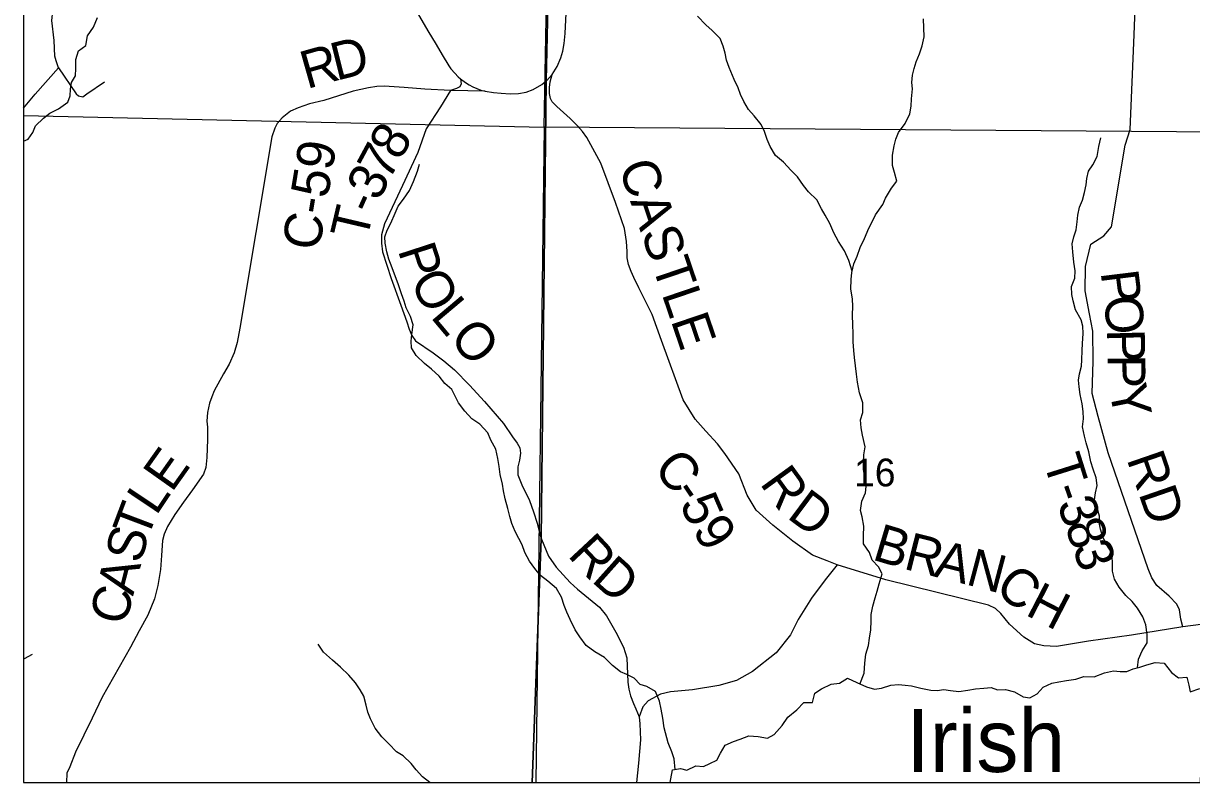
# Model space of a CAD drawing. Extents: x -3.6 to 34, y 0 to 32.8.
# Drawn here: x -3.63 to -1.871, y 26.043 to 27.186 of the extents above; entities that cross this region are included whole.
import ezdxf

# ---------------------------------------------------------------- set-up
doc = ezdxf.new("R2010")
doc.units = 0
for name, color, linetype in [('GM_X_Corporation', 7, 'Continuous'), ('GM_X_County_Road', 7, 'Continuous'), ('GM_X_County_Road_Text', 7, 'Continuous'), ('GM_X_Minor_River', 7, 'Continuous'), ('GM_X_Minor_River_Text', 7, 'Continuous'), ('GM_X_Section_Text', 7, 'Continuous'), ('GM_X_State_Route', 7, 'Continuous'), ('GM_X_Township_Road', 7, 'Continuous'), ('GM_X_Township_Road_Text', 7, 'Continuous'), ('SH_Data', 7, 'Continuous')]:
    doc.layers.add(name, color=color, linetype=linetype)

msp = doc.modelspace()

# ---------------------------------------------------------------- linework, layer by layer
at = {"layer": 'GM_X_Corporation'}
for points in [[(3.1705, 28.9337), (3.1705, 32.8429), (-3.6295, 32.8429), (-3.6295, 26.0429), (2.3706, 26.0429), (2.3712, 26.0804), (2.3716, 26.1248), (2.3732, 26.2253), (2.3789, 26.6097), (2.3911, 27.5117), (2.3952, 27.9336), (2.3997, 28.282), (2.4082, 28.9473), (2.5416, 28.945), (2.5837, 28.9442), (2.8343, 28.9397)], [(-3.6295, 30.6462), (-3.6295, 26.0429), (-2.8635, 26.0429), (-2.8499, 26.4099), (-2.8426, 27.1), (-2.8208, 28.0589), (-2.813, 28.9119), (-2.8073, 29.6484), (-2.8047, 30.129), (-2.8012, 30.524), (-2.8007, 30.6338), (-3.5736, 30.6453)], [(-3.6295, 28.0641), (-3.6295, 27.0475), (-2.8456, 27.0298), (-2.8264, 28.0607)], [(-1.8056, 28.0368), (-1.8251, 27.0226), (-2.8456, 27.0298), (-2.8264, 28.0607)], [(-2.8578, 26.0429), (-1.8572, 26.0429), (-1.8251, 27.0226), (-2.8456, 27.0298)]]:
    msp.add_lwpolyline(points, close=True, dxfattribs=at)
msp.add_lwpolyline([(-0.398, 30.5946), (-0.453, 30.5952), (-0.5034, 30.5954), (-2.3541, 30.6318), (-2.7027, 30.634), (-2.8007, 30.6338), (-2.8012, 30.524), (-2.8047, 30.129), (-2.8073, 29.6484), (-2.813, 28.9119), (-2.8208, 28.0589), (-2.8426, 27.1), (-2.8499, 26.4099), (-2.8635, 26.0429), (2.3706, 26.0429)], dxfattribs=at)
at = {"layer": 'GM_X_County_Road'}
for points in [[(-2.8374, 27.0894), (-2.8364, 27.0983), (-2.8336, 27.1093)], [(-2.9344, 27.0839), (-2.9866, 27.0853), (-3.0253, 27.0873), (-3.0563, 27.0894), (-3.0864, 27.0915), (-3.0973, 27.091), (-3.1101, 27.0892), (-3.1329, 27.0842), (-3.177, 27.0703), (-3.1988, 27.0649), (-3.2158, 27.0592), (-3.2274, 27.0538), (-3.2401, 27.0442), (-3.2476, 27.0356), (-3.2509, 27.0282), (-3.2555, 27.0153), (-3.3037, 26.7274), (-3.3074, 26.7056), (-3.3124, 26.69), (-3.3196, 26.6728), (-3.328, 26.6586), (-3.3421, 26.6328), (-3.3458, 26.624), (-3.3493, 26.6142), (-3.3525, 26.6003), (-3.3531, 26.5871), (-3.3521, 26.5782), (-3.3522, 26.5595), (-3.3532, 26.5325), (-3.355, 26.5174), (-3.3584, 26.5074), (-3.3747, 26.4838), (-3.3884, 26.4654), (-3.4014, 26.4466), (-3.4126, 26.4286), (-3.4176, 26.4169), (-3.4201, 26.4073), (-3.4217, 26.3849), (-3.4232, 26.3636), (-3.4273, 26.3396), (-3.4319, 26.3194), (-3.4422, 26.2951), (-3.4554, 26.2716), (-3.4684, 26.2471), (-3.5111, 26.1718), (-3.5261, 26.1399), (-3.5509, 26.0886), (-3.5598, 26.0668), (-3.5641, 26.057), (-3.5647, 26.0429)], [(-2.4042, 26.3707), (-2.4195, 26.3771), (-2.4415, 26.3853), (-2.4713, 26.4065), (-2.501, 26.4306), (-2.5265, 26.453), (-2.5399, 26.4759), (-2.5524, 26.5078), (-2.5735, 26.5387), (-2.5847, 26.5529), (-2.6022, 26.5721), (-2.6179, 26.5902), (-2.6364, 26.6191), (-2.669, 26.7088), (-2.6829, 26.7477), (-2.703, 26.7882), (-2.7105, 26.8036), (-2.7147, 26.8128), (-2.7183, 26.8231), (-2.7204, 26.8333), (-2.7205, 26.8429), (-2.7213, 26.8578), (-2.7247, 26.8774), (-2.7381, 26.9164), (-2.7601, 26.9755), (-2.7811, 27.0144), (-2.7876, 27.0234), (-2.7952, 27.032), (-2.8061, 27.0428), (-2.8266, 27.0608), (-2.8335, 27.068), (-2.8359, 27.0729), (-2.8375, 27.0806), (-2.8376, 27.0874), (-2.8374, 27.0894)], [(-1.8412, 26.2831), (-1.8841, 26.2773), (-1.9612, 26.2647), (-2.026, 26.256), (-2.0741, 26.248), (-2.0933, 26.2489), (-2.1071, 26.2519), (-2.1231, 26.262), (-2.145, 26.2816), (-2.1578, 26.2974), (-2.1662, 26.3053), (-2.1763, 26.3099), (-2.3309, 26.3483), (-2.4042, 26.3707), (-2.4223, 26.3481), (-2.4431, 26.3204), (-2.4631, 26.2886), (-2.4748, 26.2655), (-2.4964, 26.2381), (-2.5316, 26.2104), (-2.5559, 26.1968), (-2.5824, 26.1893), (-2.6222, 26.1828), (-2.6551, 26.1798), (-2.6702, 26.1761), (-2.689, 26.1659), (-2.6967, 26.1571), (-2.7022, 26.1421), (-2.7013, 26.1316), (-2.7004, 26.1071), (-2.7034, 26.0721), (-2.7066, 26.0429)]]:
    msp.add_lwpolyline(points, dxfattribs=at)
at = {"layer": 'GM_X_Minor_River'}
for points in [[(-3.6295, 27.0086), (-3.6225, 27.0117), (-3.6151, 27.022), (-3.6115, 27.032), (-3.5992, 27.0435), (-3.5895, 27.0509), (-3.5764, 27.0576), (-3.5625, 27.0677), (-3.5593, 27.0772), (-3.5587, 27.0871), (-3.557, 27.097), (-3.5511, 27.107), (-3.5505, 27.118), (-3.5504, 27.1316), (-3.5464, 27.145), (-3.5356, 27.1531), (-3.5328, 27.1672), (-3.5239, 27.1806), (-3.5177, 27.1948)], [(-2.3817, 26.8129), (-2.3866, 26.8293), (-2.3933, 26.8436), (-2.4022, 26.8579), (-2.4093, 26.8706), (-2.4152, 26.8846), (-2.4222, 26.8974), (-2.428, 26.9071), (-2.4351, 26.9203), (-2.4474, 26.9326), (-2.4551, 26.9423), (-2.464, 26.9551), (-2.4737, 26.9644), (-2.4852, 26.9771), (-2.4971, 26.9872), (-2.5053, 27.0007), (-2.5096, 27.0112), (-2.5136, 27.0233), (-2.5187, 27.0338), (-2.5295, 27.0469), (-2.5377, 27.0567), (-2.545, 27.0683), (-2.5498, 27.0792), (-2.5533, 27.089), (-2.5592, 27.1018), (-2.5671, 27.1195), (-2.5707, 27.1309), (-2.5728, 27.1411), (-2.576, 27.152), (-2.5807, 27.1633), (-2.5923, 27.1756), (-2.6019, 27.1838), (-2.6146, 27.1969)], [(-2.3702, 26.1913), (-2.3638, 26.2077), (-2.3629, 26.2229), (-2.3613, 26.2362), (-2.3573, 26.2495), (-2.3556, 26.2602), (-2.3535, 26.2728), (-2.3534, 26.2864), (-2.3532, 26.2959), (-2.3507, 26.3085), (-2.3472, 26.3211), (-2.3443, 26.331), (-2.3411, 26.342), (-2.3368, 26.3573), (-2.3419, 26.3678), (-2.3515, 26.3779), (-2.3559, 26.3892), (-2.3648, 26.4027), (-2.3646, 26.4145), (-2.3641, 26.4289), (-2.3666, 26.4429), (-2.369, 26.4527), (-2.3674, 26.4668), (-2.3615, 26.4791), (-2.3609, 26.4886), (-2.3622, 26.5003), (-2.3647, 26.5143), (-2.3649, 26.5253), (-2.3644, 26.5363), (-2.3623, 26.5485), (-2.366, 26.5659), (-2.3684, 26.5772), (-2.369, 26.589), (-2.3658, 26.6004), (-2.3657, 26.6148), (-2.3705, 26.6299), (-2.3737, 26.6458), (-2.3751, 26.6579), (-2.3768, 26.6704), (-2.3781, 26.6829), (-2.3791, 26.6936), (-2.3801, 26.7068), (-2.3803, 26.7197), (-2.3808, 26.7315), (-2.3811, 26.7474), (-2.3809, 26.7596), (-2.3811, 26.7713), (-2.3836, 26.7861), (-2.3831, 26.8005), (-2.3822, 26.8108), (-2.3794, 26.8241), (-2.3742, 26.8356), (-2.3695, 26.8489), (-2.3633, 26.8623), (-2.3568, 26.8776), (-2.3509, 26.8883), (-2.3465, 26.8979), (-2.3354, 26.9133), (-2.3318, 26.9232), (-2.3226, 26.9378), (-2.3144, 26.9485), (-2.318, 26.9618), (-2.3209, 26.9723), (-2.3211, 26.9879), (-2.3183, 27.0016), (-2.3158, 27.0119), (-2.3118, 27.0218), (-2.3022, 27.0356), (-2.2949, 27.0498), (-2.2928, 27.0616), (-2.2926, 27.0726), (-2.291, 27.0874), (-2.2919, 27.0973), (-2.291, 27.1083), (-2.2885, 27.1182), (-2.2852, 27.1281), (-2.2805, 27.1404), (-2.2762, 27.1526), (-2.2734, 27.1659), (-2.274, 27.1796), (-2.2742, 27.1932)], [(-1.952, 26.2158), (-1.9508, 26.2287), (-1.945, 26.2414), (-1.9376, 26.2536), (-1.9375, 26.2661), (-1.9396, 26.2805), (-1.9443, 26.2926), (-1.9521, 26.3054), (-1.9602, 26.3155), (-1.9699, 26.3248), (-1.9799, 26.3371), (-1.9869, 26.3492), (-1.9898, 26.3613), (-1.9896, 26.3749), (-1.991, 26.3889), (-1.9988, 26.4017), (-2.0046, 26.413), (-2.0078, 26.4247), (-2.0099, 26.4345), (-2.0093, 26.444), (-2.0129, 26.4565), (-2.0169, 26.4686), (-2.0152, 26.4792), (-2.0127, 26.4903), (-2.0144, 26.5016), (-2.0188, 26.5149), (-2.0224, 26.5258), (-2.0257, 26.5409), (-2.0293, 26.5545), (-2.0321, 26.5647), (-2.035, 26.5787), (-2.0333, 26.5909), (-2.0342, 26.6015), (-2.0356, 26.6132), (-2.0385, 26.6272), (-2.0402, 26.639), (-2.0411, 26.6488), (-2.0397, 26.6583), (-2.0365, 26.6698), (-2.0359, 26.6793), (-2.0354, 26.6937), (-2.0348, 26.7043), (-2.0339, 26.7192), (-2.0345, 26.7302), (-2.0369, 26.74), (-2.0455, 26.755), (-2.0491, 26.7682), (-2.0512, 26.7781), (-2.0514, 26.7898), (-2.0466, 26.8024), (-2.0461, 26.8135), (-2.0478, 26.8267), (-2.0496, 26.8422), (-2.0505, 26.854), (-2.0481, 26.865), (-2.0444, 26.8753), (-2.0431, 26.8871), (-2.0422, 26.8974), (-2.0397, 26.9092), (-2.035, 26.9199), (-2.0318, 26.9317), (-2.0293, 26.9432), (-2.0283, 26.9527), (-2.0262, 26.9637), (-2.0196, 26.9733), (-2.013, 26.9859), (-2.0106, 27.0008), (-2.0074, 27.0137)], [(-2.648, 26.0628), (-2.6497, 26.0788), (-2.6533, 26.0894), (-2.6588, 26.1026), (-2.6648, 26.1252), (-2.6666, 26.14), (-2.6691, 26.1536), (-2.6719, 26.1653), (-2.6779, 26.18), (-2.6909, 26.1874), (-2.7008, 26.1906), (-2.71, 26.2003), (-2.7211, 26.2058), (-2.7306, 26.2099), (-2.7425, 26.2195), (-2.7544, 26.2315), (-2.7693, 26.2399), (-2.7824, 26.2496), (-2.792, 26.2623), (-2.7987, 26.2732), (-2.8061, 26.2886), (-2.8112, 26.2996), (-2.8155, 26.3097), (-2.8192, 26.3222), (-2.8269, 26.3353), (-2.84, 26.3461), (-2.8511, 26.3547), (-2.8596, 26.3655), (-2.8674, 26.3764), (-2.8748, 26.3892), (-2.8788, 26.4009), (-2.8835, 26.4107), (-2.8889, 26.4208), (-2.8941, 26.4329), (-2.8973, 26.4434), (-2.9001, 26.4555), (-2.9041, 26.4703), (-2.9066, 26.4824), (-2.9083, 26.4922), (-2.9116, 26.5069), (-2.9133, 26.5187), (-2.9154, 26.5312), (-2.9183, 26.5448), (-2.9257, 26.5587), (-2.9304, 26.5696), (-2.9424, 26.5827), (-2.9546, 26.5908), (-2.965, 26.6024), (-2.9743, 26.6148), (-2.9845, 26.6351), (-2.9949, 26.644), (-3.0037, 26.6549), (-3.0153, 26.6657), (-3.0256, 26.6739), (-3.038, 26.6862), (-3.0453, 26.6978), (-3.0459, 26.7077), (-3.0449, 26.7179), (-3.0425, 26.732), (-3.0469, 26.7448), (-3.0532, 26.7576), (-3.056, 26.7678), (-3.0603, 26.7791), (-3.0651, 26.7938), (-3.0695, 26.8044), (-3.0742, 26.818), (-3.0794, 26.8312), (-3.0822, 26.8421), (-3.0847, 26.855), (-3.0852, 26.8648), (-3.082, 26.8748), (-3.0765, 26.8851), (-3.0699, 26.9004), (-3.0652, 26.9111), (-3.057, 26.9215), (-3.0482, 26.9345), (-3.0423, 26.9479), (-3.0361, 26.9636), (-3.0329, 26.9742)], [(-3.0175, 26.0429), (-3.0177, 26.043), (-3.0285, 26.0516), (-3.0381, 26.062), (-3.0455, 26.0718), (-3.0578, 26.0833), (-3.0677, 26.0892), (-3.0793, 26.1012), (-3.0897, 26.112), (-3.1001, 26.1251), (-3.1068, 26.1387), (-3.1107, 26.1492), (-3.1135, 26.1594), (-3.1172, 26.173), (-3.1226, 26.1828), (-3.1293, 26.1933), (-3.1397, 26.2049), (-3.152, 26.2168), (-3.1643, 26.2272), (-3.1777, 26.2391), (-3.1855, 26.2515)], [(-3.6295, 26.2293), (-3.628, 26.23), (-3.616, 26.2363)], [(-2.6558, 26.0429), (-2.6549, 26.0488), (-2.6524, 26.0621), (-2.6404, 26.0642), (-2.6305, 26.0617), (-2.6173, 26.0684), (-2.6056, 26.067), (-2.5958, 26.0718), (-2.5853, 26.0769), (-2.5798, 26.0872), (-2.5732, 26.0994), (-2.5604, 26.1046), (-2.5506, 26.1082), (-2.5371, 26.1133), (-2.5231, 26.1124), (-2.5094, 26.11), (-2.4993, 26.1155), (-2.487, 26.129), (-2.4785, 26.1416), (-2.4651, 26.1525), (-2.4543, 26.1637), (-2.4414, 26.1635), (-2.4379, 26.1776), (-2.4281, 26.1842), (-2.4135, 26.1913), (-2.4006, 26.1927), (-2.3887, 26.2001), (-2.3749, 26.1935), (-2.3604, 26.1869), (-2.3479, 26.1837), (-2.3377, 26.185), (-2.3234, 26.1894), (-2.312, 26.1904), (-2.3018, 26.1898), (-2.2923, 26.1888), (-2.2786, 26.1849), (-2.2635, 26.1821), (-2.2536, 26.1815), (-2.2438, 26.1832), (-2.2339, 26.1814), (-2.2214, 26.1801), (-2.2078, 26.1819), (-2.1961, 26.184), (-2.1833, 26.1853), (-2.1727, 26.1863), (-2.1632, 26.1826), (-2.1507, 26.1832), (-2.1374, 26.1797), (-2.1244, 26.1723), (-2.1145, 26.1706), (-2.1033, 26.1764), (-2.094, 26.1865), (-2.0812, 26.1924), (-2.0706, 26.1948), (-2.0593, 26.1965), (-2.045, 26.1987), (-2.0329, 26.2027), (-2.0174, 26.2022), (-2.002, 26.2081), (-1.9884, 26.2114), (-1.9785, 26.21), (-1.9683, 26.2102), (-1.9585, 26.2142), (-1.9487, 26.2166), (-1.9382, 26.2202), (-1.9254, 26.2239), (-1.9118, 26.2226), (-1.9009, 26.2087), (-1.8906, 26.2005), (-1.8777, 26.2019), (-1.8749, 26.1894), (-1.8728, 26.1796), (-1.8585, 26.1848)]]:
    msp.add_lwpolyline(points, dxfattribs=at)
at = {"layer": 'GM_X_State_Route'}
msp.add_lwpolyline([(-3.0456, 27.2179), (-3.0208, 27.1751), (-3.0081, 27.1545), (-2.9988, 27.1386), (-2.9891, 27.1225), (-2.9859, 27.1178), (-2.9801, 27.111), (-2.9751, 27.1059), (-2.9716, 27.1028), (-2.9641, 27.097), (-2.9586, 27.0935), (-2.9527, 27.0904), (-2.9409, 27.0856), (-2.9344, 27.0839), (-2.9218, 27.0821), (-2.9101, 27.0809), (-2.8966, 27.0803), (-2.884, 27.0808), (-2.8728, 27.0828), (-2.8618, 27.0867), (-2.8489, 27.094), (-2.8424, 27.0995), (-2.8414, 27.1003), (-2.8336, 27.1093), (-2.8258, 27.1212), (-2.8203, 27.1345), (-2.8173, 27.1441), (-2.8151, 27.1558), (-2.8139, 27.1708), (-2.8121, 27.2014)], dxfattribs=at)
at = {"layer": 'GM_X_Township_Road'}
for points in [[(-1.8841, 26.2773), (-1.8867, 26.289), (-1.8891, 26.3032), (-1.893, 26.3118), (-1.9046, 26.3235), (-1.923, 26.3398), (-1.9305, 26.3515), (-1.9361, 26.3649), (-1.9962, 26.5393), (-2.0112, 26.594), (-2.0202, 26.6287), (-2.019, 26.6774), (-2.0193, 26.7226), (-2.0246, 26.7487), (-2.031, 26.7835), (-2.0303, 26.82), (-2.0222, 26.8538), (-2.0028, 26.8665), (-1.9915, 26.8798), (-1.971, 27.0029), (-1.9634, 27.0263), (-1.9572, 27.1691), (-1.9507, 27.3404)], [(-3.6295, 27.0587), (-3.6118, 27.0796), (-3.5767, 27.1193), (-3.58, 27.1298), (-3.5822, 27.1366), (-3.583, 27.1606), (-3.5865, 27.1905), (-3.585, 27.2048), (-3.58, 27.2235), (-3.575, 27.2428), (-3.574, 27.2509), (-3.5759, 27.2652), (-3.5808, 27.2838), (-3.5822, 27.2913), (-3.5826, 27.2968), (-3.5826, 27.3011), (-3.5804, 27.3049), (-3.5739, 27.3089)], [(-3.5767, 27.1193), (-3.5502, 27.0801), (-3.5464, 27.077), (-3.5401, 27.0756), (-3.534, 27.0799), (-3.5074, 27.0983)], [(-2.9716, 27.1028), (-2.9704, 27.0951), (-2.9723, 27.0908), (-2.9776, 27.0879), (-2.9866, 27.0853), (-3.0015, 27.0607), (-3.0232, 27.0273), (-3.0357, 26.9919), (-3.0588, 26.9422), (-3.0858, 26.8841), (-3.0903, 26.868), (-3.0905, 26.8552), (-3.089, 26.842), (-3.0757, 26.8018), (-3.0611, 26.7621), (-3.0523, 26.737), (-3.0489, 26.7255), (-3.0449, 26.7163), (-3.0393, 26.7083), (-3.0128, 26.6901), (-2.9965, 26.6782), (-2.9807, 26.6644), (-2.9579, 26.6413), (-2.9354, 26.6167), (-2.9069, 26.5836), (-2.8931, 26.5635), (-2.8861, 26.5543), (-2.8821, 26.5469), (-2.8812, 26.5389), (-2.8828, 26.5284), (-2.8853, 26.5183), (-2.8851, 26.5066), (-2.879, 26.4912), (-2.8676, 26.4677), (-2.8617, 26.4509), (-2.8559, 26.4334), (-2.8526, 26.4198)], [(-2.8526, 26.4198), (-2.8519, 26.4169), (-2.8497, 26.4093), (-2.8389, 26.384), (-2.8273, 26.3671), (-2.8061, 26.344), (-2.7953, 26.3343), (-2.7789, 26.3204), (-2.7622, 26.307), (-2.7514, 26.2939), (-2.7374, 26.2694), (-2.7259, 26.2469), (-2.721, 26.2307), (-2.7197, 26.1942), (-2.7182, 26.1838), (-2.7153, 26.1737), (-2.7108, 26.162), (-2.7073, 26.1542), (-2.7022, 26.1421)]]:
    msp.add_lwpolyline(points, dxfattribs=at)
at = {"layer": 'SH_Data'}
for p, q in [((-3.6295, 32.8429), (-3.6295, 26.0429)), ((-3.6295, 26.0429), (3.1705, 26.0429)), ((-3.6295, 26.0429), (-3.6295, 26.0429))]:
    msp.add_line(p, q, dxfattribs=at)

# ---------------------------------------------------------------- texts
at = {"layer": 'GM_X_County_Road_Text'}
for s, height, rotation, p in [('D', 0.0568, 14.0769, (-3.1584, 27.0997)), ('R', 0.0568, 15.8379, (-3.2028, 27.0871)), ('C-59', 0.05682, 80.7079, (-3.1843, 26.8422)), ('CASTLE', 0.05682, 288.7732, (-2.734, 26.9709)), ('E', 0.0568, 54.6551, (-3.4062, 26.4786)), ('C', 0.0568, 310.2546, (-2.6828, 26.515)), ('R', 0.0568, 305.9726, (-2.5219, 26.4934)), ('-', 0.0568, 304.0321, (-2.6536, 26.4807)), ('L', 0.0568, 56.1138, (-3.4297, 26.4437)), ('5', 0.0568, 293.311, (-2.6419, 26.4638)), ('D', 0.0568, 323.3497, (-2.4816, 26.4425)), ('T', 0.0568, 69.2714, (-3.4431, 26.407)), ('9', 0.0568, 302.5732, (-2.6234, 26.4228)), ('S', 0.0568, 75.6088, (-3.4522, 26.3714)), ('B', 0.0568, 343.3976, (-2.3533, 26.3792)), ('R', 0.0568, 345.8477, (-2.306, 26.3652)), ('A', 0.0568, 346.027, (-2.2606, 26.3537)), ('N', 0.0568, 345.1562, (-2.2123, 26.3417)), ('A', 0.0568, 75.8052, (-3.4644, 26.323)), ('C', 0.0568, 321.7468, (-2.1694, 26.3316)), ('C', 0.0568, 75.8123, (-3.4758, 26.2778)), ('H', 0.0568, 332.7248, (-2.1228, 26.2963))]:
    msp.add_text(s, height=height, rotation=rotation, dxfattribs=at).set_placement(p)
at = {"layer": 'GM_X_Minor_River_Text'}
msp.add_text('Irish', height=0.0947, rotation=359.9605, dxfattribs=at).set_placement((-2.3002, 26.059))
at = {"layer": 'GM_X_Section_Text'}
msp.add_text('16', height=0.04186, rotation=0, dxfattribs=at).set_placement((-2.3788, 26.489))
at = {"layer": 'GM_X_Township_Road_Text'}
for s, height, rotation, p in [('8', 0.0568, 59.9493, (-3.0632, 26.9777)), ('7', 0.0568, 61.7272, (-3.0794, 26.9475)), ('3', 0.0568, 63.8192, (-3.0945, 26.9168)), ('T', 0.0568, 76.77, (-3.1126, 26.8577)), ('-', 0.0568, 65.6875, (-3.1038, 26.8962)), ('P', 0.0568, 288.0285, (-3.0662, 26.8448)), ('O', 0.0568, 299.9514, (-3.0491, 26.7966)), ('P', 0.0568, 277.1121, (-2.0078, 26.8117)), ('L', 0.0568, 310.0715, (-3.0178, 26.7443)), ('O', 0.0568, 275.7726, (-2.0031, 26.774)), ('O', 0.0568, 310.9275, (-2.9899, 26.7111)), ('P', 0.0568, 271.5539, (-1.9982, 26.7254)), ('P', 0.0568, 270.4419, (-1.9971, 26.6874)), ('Y', 0.0568, 281.3429, (-1.9956, 26.6373)), ('T', 0.0568, 287.4808, (-2.0946, 26.5275)), ('RD', 0.05682, 289.0568, (-1.9689, 26.5304)), ('-', 0.0568, 288.9306, (-2.0813, 26.4855)), ('3', 0.0568, 289.1955, (-2.0737, 26.4631)), ('8', 0.0568, 289.2775, (-2.0621, 26.43)), ('R', 0.0568, 313.0167, (-2.8115, 26.3846)), ('3', 0.0568, 289.2999, (-2.0506, 26.3969)), ('D', 0.0568, 318.2306, (-2.7757, 26.3466))]:
    msp.add_text(s, height=height, rotation=rotation, dxfattribs=at).set_placement(p)

doc.saveas('drawing.dxf')
